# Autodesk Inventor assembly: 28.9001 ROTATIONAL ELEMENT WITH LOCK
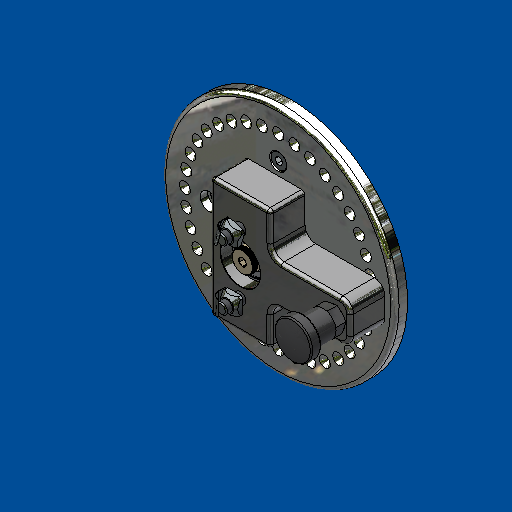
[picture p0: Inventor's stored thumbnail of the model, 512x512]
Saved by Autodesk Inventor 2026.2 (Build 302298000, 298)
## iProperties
Created: 2022-08
Part Number: 28.9001 ROTATIONAL ELEMENT WITH LOCK
Document SubType Name: Assembly
Designer: amoles
Description: ROTATIONAL ELEMENT WITH LOCK
Stock Number: 28.9001 ROTATIONAL ELEMENT WITH LOCK
Author: amoles
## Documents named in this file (10)
- L:\INVENTOR LIBRARIES\PARTS LIBRARY\LINKS AND HINGES\28.9001 ROTATIONAL ELEMENT WITH LOCK.iam
- L:\INVENTOR LIBRARIES\PARTS LIBRARY\MACHINE ELEMENTS\BALL BEARINGS\50.9102 5200 2RS DOUBLE ROW ANGULAR CONTACT BEARING 10mm ID - 30MM OD.iam
- L:\INVENTOR LIBRARIES\PARTS LIBRARY\FASTENING ELEMENTS\NUTS\21.1351_2 M8 SQUARE NUT POS FXG.ipt
- L:\INVENTOR LIBRARIES\PARTS LIBRARY\FASTENING ELEMENTS\SCREWS CAP\21.1208 M8X35.ipt
- L:\INVENTOR LIBRARIES\PARTS LIBRARY\INDEXING POSITIONING AND FIXTURING\SUBCOMPONENTS\28.9001-2 SPRING PLUNGER CATCH DISC.ipt
- L:\INVENTOR LIBRARIES\PARTS LIBRARY\INDEXING POSITIONING AND FIXTURING\SUBCOMPONENTS\28.9001-4 ROTATIONAL ELEMENT BEARING PLATE DOUBLE ROW BEARING.ipt
- L:\INVENTOR LIBRARIES\PARTS LIBRARY\INDEXING POSITIONING AND FIXTURING\29.0855_9 SPRING PLUNGER M16.ipt
- L:\INVENTOR LIBRARIES\PARTS LIBRARY\INDEXING POSITIONING AND FIXTURING\SUBCOMPONENTS\28.9001-3 ROTATIONAL ELEMENT WASHER.ipt
- L:\INVENTOR LIBRARIES\PARTS LIBRARY\FASTENING ELEMENTS\SCREWS CAP\21.1200 M8X16.ipt
- L:\INVENTOR LIBRARIES\PARTS LIBRARY\FASTENING ELEMENTS\SHOULDER SCREWS\21.9608_16 M8 SHOULDER BOLT 16mm.ipt
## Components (14 placed, 9 different names)
1. 21.1351_2 M8 SQUARE NUT POS FXG:3 — Insert:24
2. 21.1351_2 M8 SQUARE NUT POS FXG:4 — Insert:25
3. 21.1208  M8 x 35:1 — Insert:22
4. 21.1208  M8 x 35:2 — Insert:23
5. 28.9001-3 ROTATIONAL ELEMENT WASHER:1
6. 28.9001-2 SPRING PLUNGER CATCH DISC:1 — Mate:7, Insert:26, Insert:27, Insert:28, Insert:29
7. 28.9001-4 ROTATIONAL ELEMENT BEARING PLATE DOUBLE ROW BEARING:1 — Insert:18, Insert:19, Insert:22, Insert:23, Insert:24, Insert:25
8. 29.0855_9 SPRING PLUNGER M16:1 — Mate:7, Insert:19
9. 50.9102 5200 2RS DOUBLE ROW ANGULAR CONTACT BEARING 10mm ID - 30MM OD:2 [sub-assembly] — Insert:18, Insert:21
10. 21.9608_16 M8 SHOULDER BOLT 16mm:1 — Insert:21
11. 21.1200 M8 x 16:1 — Insert:26
12. 21.1200 M8 x 16:2 — Insert:27
13. 21.1351_2 M8 SQUARE NUT POS FXG:5 — Insert:28
14. 21.1351_2 M8 SQUARE NUT POS FXG:6 — Insert:29
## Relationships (12: Insert 11, Mate 1)
- Mate:7: 28.9001-2 SPRING PLUNGER CATCH DISC:1 ↔ 29.0855_9 SPRING PLUNGER M16:1
- Insert:18: 28.9001-4 ROTATIONAL ELEMENT BEARING PLATE DOUBLE ROW BEARING:1 ↔ 50.9102 5200 2RS DOUBLE ROW ANGULAR CONTACT BEARING 10mm ID - 30MM OD:2
- Insert:19: 28.9001-4 ROTATIONAL ELEMENT BEARING PLATE DOUBLE ROW BEARING:1 ↔ 29.0855_9 SPRING PLUNGER M16:1
- Insert:21: 50.9102 5200 2RS DOUBLE ROW ANGULAR CONTACT BEARING 10mm ID - 30MM OD:2 ↔ 21.9608_16 M8 SHOULDER BOLT 16mm:1
- Insert:22: 21.1208  M8 x 35:1 ↔ 28.9001-4 ROTATIONAL ELEMENT BEARING PLATE DOUBLE ROW BEARING:1
- Insert:23: 21.1208  M8 x 35:2 ↔ 28.9001-4 ROTATIONAL ELEMENT BEARING PLATE DOUBLE ROW BEARING:1
- Insert:24: 21.1351_2 M8 SQUARE NUT POS FXG:3 ↔ 28.9001-4 ROTATIONAL ELEMENT BEARING PLATE DOUBLE ROW BEARING:1
- Insert:25: 21.1351_2 M8 SQUARE NUT POS FXG:4 ↔ 28.9001-4 ROTATIONAL ELEMENT BEARING PLATE DOUBLE ROW BEARING:1
- Insert:26: 28.9001-2 SPRING PLUNGER CATCH DISC:1 ↔ 21.1200 M8 x 16:1
- Insert:27: 28.9001-2 SPRING PLUNGER CATCH DISC:1 ↔ 21.1200 M8 x 16:2
- Insert:28: 28.9001-2 SPRING PLUNGER CATCH DISC:1 ↔ 21.1351_2 M8 SQUARE NUT POS FXG:5
- Insert:29: 28.9001-2 SPRING PLUNGER CATCH DISC:1 ↔ 21.1351_2 M8 SQUARE NUT POS FXG:6
